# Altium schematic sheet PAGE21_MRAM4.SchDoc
size 381 x 381 mm; SheetNumber: 22; SheetTotal: 28
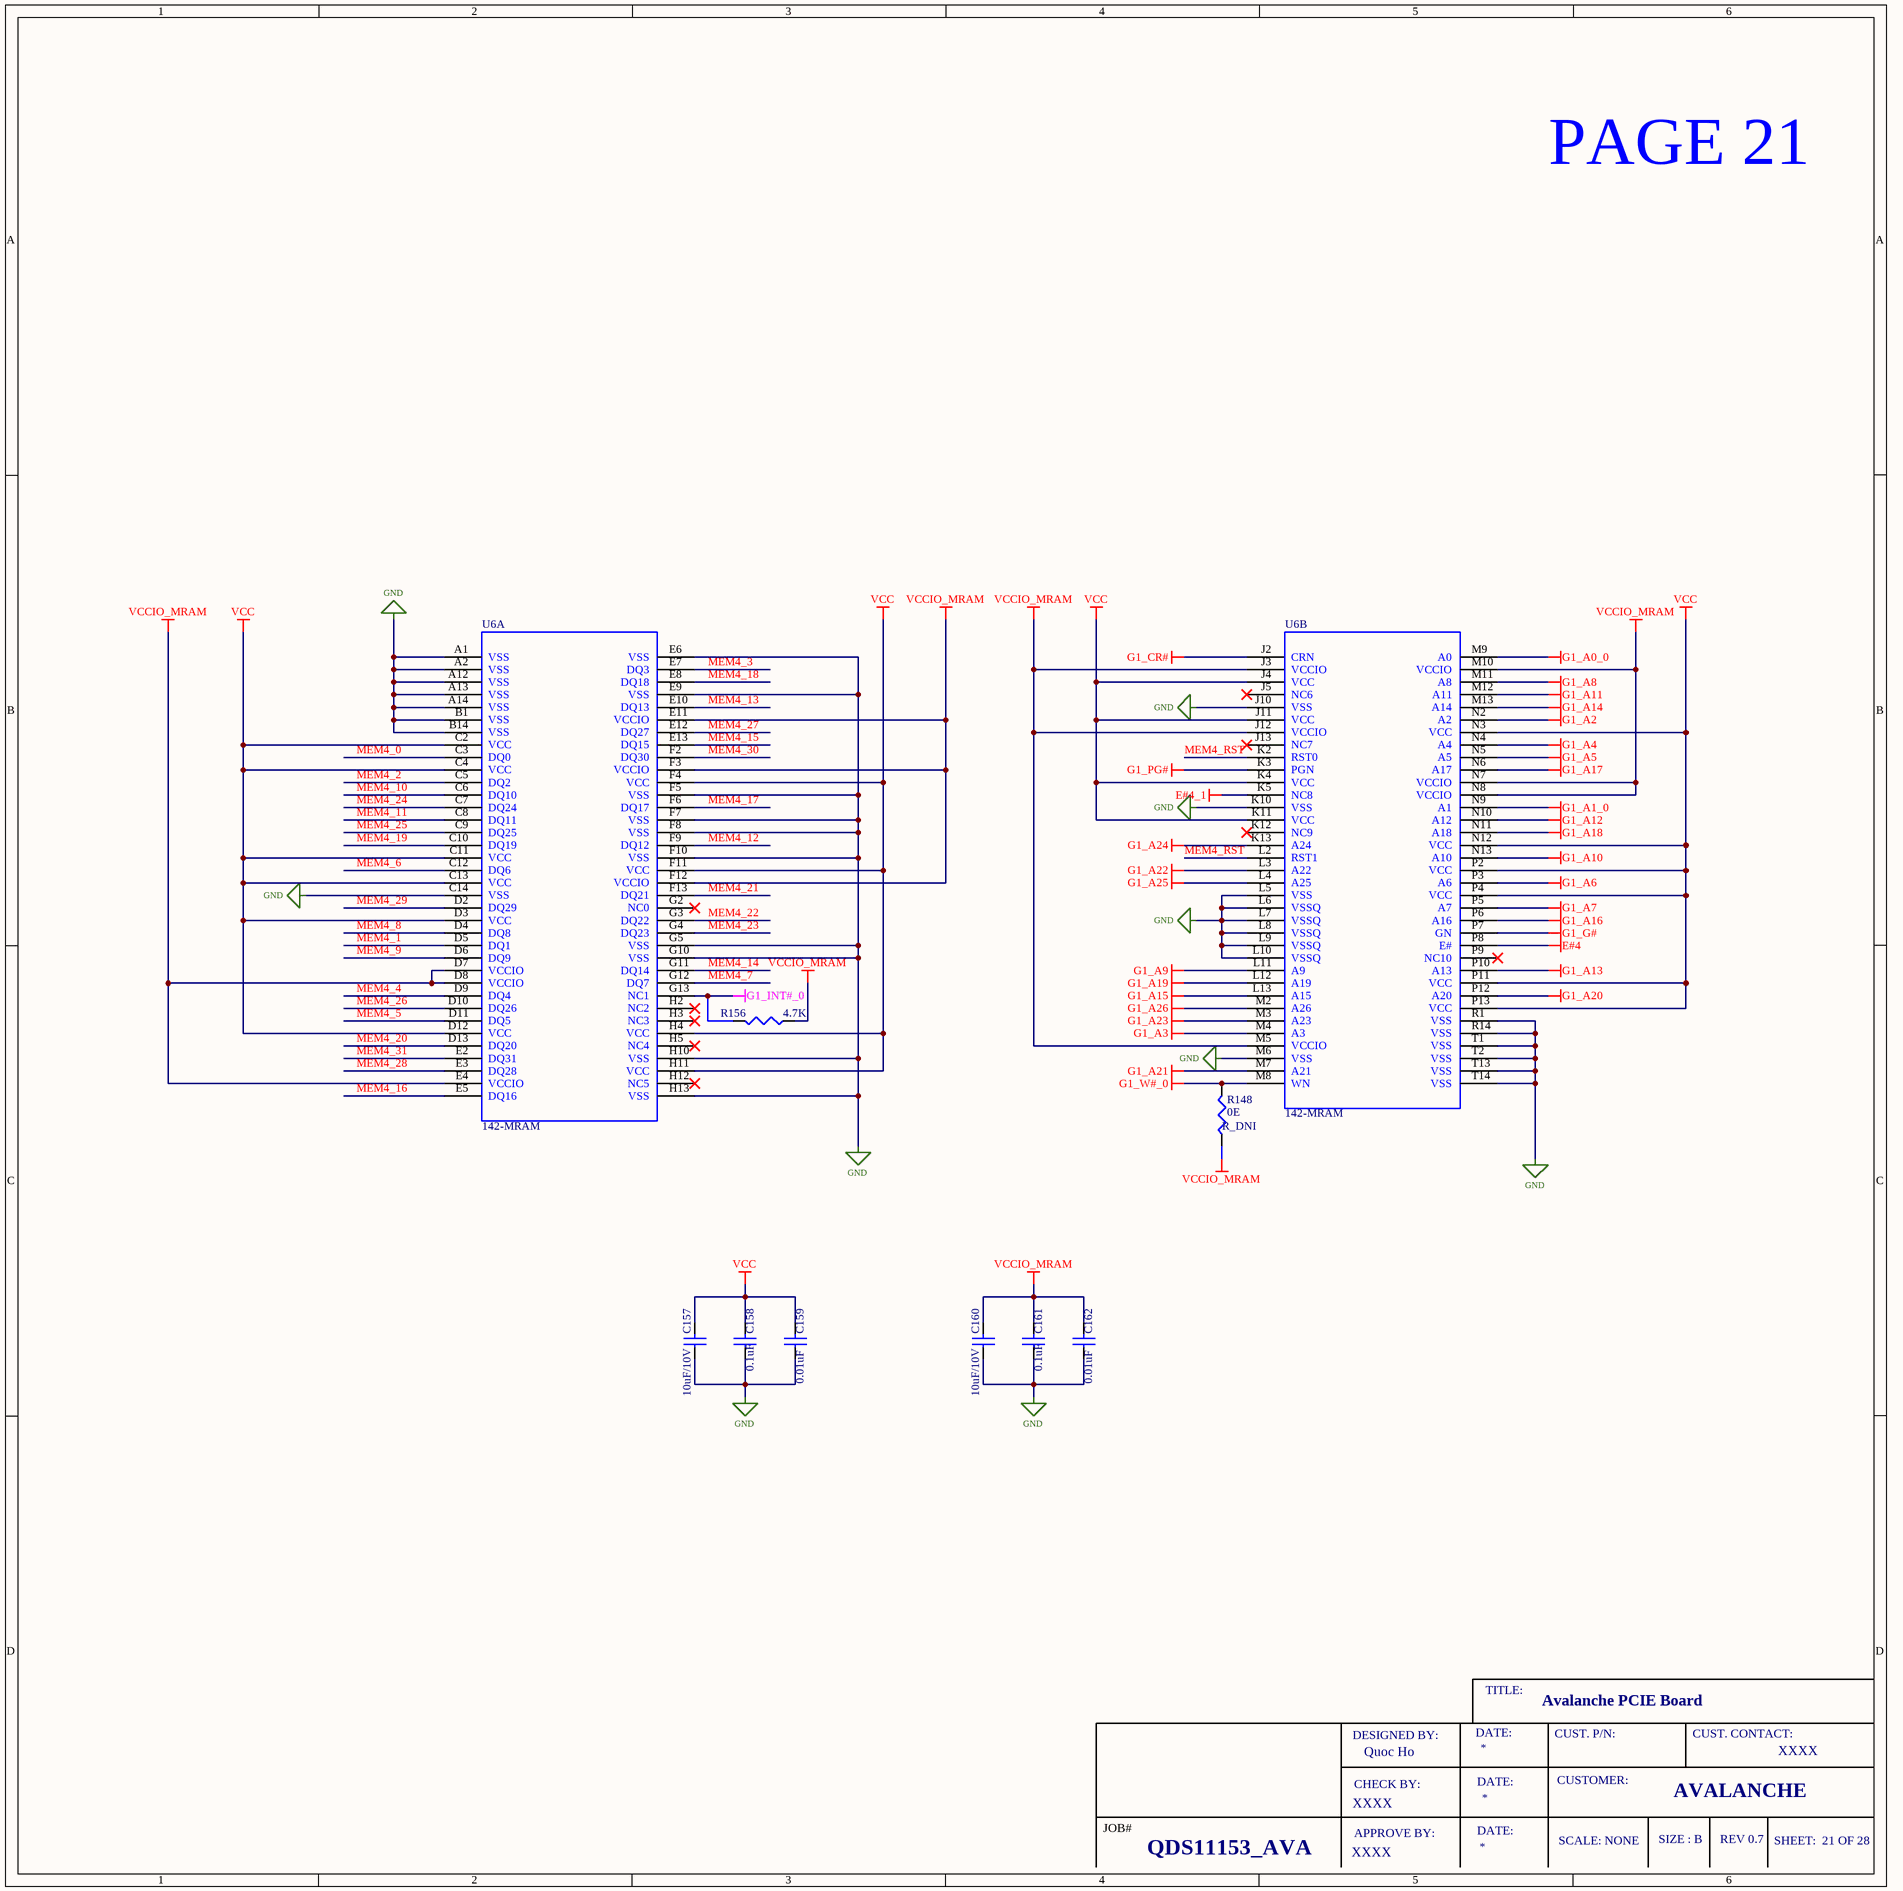
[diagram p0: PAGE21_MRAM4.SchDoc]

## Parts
C157  10uF/10V  [CN_0402]
C158  0.1uF  [CN_0402]
C159  0.01uF  [CN_0402]
C160  10uF/10V  [CN_0402]
C161  0.1uF  [CN_0402]
C162  0.01uF  [CN_0402]
R148  0E  [RN_0402]
R156  4.7K  [RN_0402]
U6  142-MRAM  [142-MRAM]  (parts A,B of 2)

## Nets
E#4: U6.P8(E#)
E#4_1: U6.K5(NC8)
G1_A0_0: U6.M9(A0)
G1_A1_0: U6.N9(A1)
G1_A2: U6.N2(A2)
G1_A3: U6.M4(A3)
G1_A4: U6.N4(A4)
G1_A5: U6.N5(A5)
G1_A6: U6.P3(A6)
G1_A7: U6.P5(A7)
G1_A8: U6.M11(A8)
G1_A9: U6.L11(A9)
G1_A10: U6.N13(A10)
G1_A11: U6.M12(A11)
G1_A12: U6.N10(A12)
G1_A13: U6.P10(A13)
G1_A14: U6.M13(A14)
G1_A15: U6.L13(A15)
G1_A16: U6.P6(A16)
G1_A17: U6.N6(A17)
G1_A18: U6.N11(A18)
G1_A19: U6.L12(A19)
G1_A20: U6.P12(A20)
G1_A21: U6.M7(A21)
G1_A22: U6.L3(A22)
G1_A23: U6.M3(A23)
G1_A24: U6.K13(A24)
G1_A25: U6.L4(A25)
G1_A26: U6.M2(A26)
G1_CR#: U6.J2(CRN)
G1_G#: U6.P7(GN)
G1_INT#_0: R156.2 U6.G13(NC1)
G1_PG#: U6.K3(PGN)
G1_W#_0: R148.2 U6.M8(WN)
GND: C157.1 C158.1 C159.1 C160.1 C161.1 C162.1 U6.A1(VSS) U6.A2(VSS) U6.A12(VSS) U6.A13(VSS) U6.A14(VSS) U6.B1(VSS) U6.B14(VSS) U6.C14(VSS) U6.E6(VSS) U6.E9(VSS) U6.F5(VSS) U6.F7(VSS) U6.F8(VSS) U6.F10(VSS) U6.G5(VSS) U6.G10(VSS) U6.H10(VSS) U6.H13(VSS) U6.J10(VSS) U6.K10(VSS) U6.L5(VSS) U6.L6(VSSQ) U6.L7(VSSQ) U6.L8(VSSQ) U6.L9(VSSQ) U6.L10(VSSQ) U6.M6(VSS) U6.R1(VSS) U6.R14(VSS) U6.T1(VSS) U6.T2(VSS) U6.T13(VSS) U6.T14(VSS)
VCC: C157.2 C158.2 C159.2 U6.C2(VCC) U6.C4(VCC) U6.C11(VCC) U6.C13(VCC) U6.D3(VCC) U6.D12(VCC) U6.F4(VCC) U6.F11(VCC) U6.H4(VCC) U6.H11(VCC) U6.J4(VCC) U6.J11(VCC) U6.K4(VCC) U6.K11(VCC) U6.N3(VCC) U6.N12(VCC) U6.P2(VCC) U6.P4(VCC) U6.P11(VCC) U6.P13(VCC)
VCCIO_MRAM: C160.2 C161.2 C162.2 R148.1 R156.1 U6.D7(VCCIO) U6.D8(VCCIO) U6.E4(VCCIO) U6.E11(VCCIO) U6.F3(VCCIO) U6.F12(VCCIO) U6.J3(VCCIO) U6.J12(VCCIO) U6.M5(VCCIO) U6.M10(VCCIO) U6.N7(VCCIO) U6.N8(VCCIO)
MEM4_0: U6.C3(DQ0)
MEM4_1: U6.D5(DQ1)
MEM4_2: U6.C5(DQ2)
MEM4_3: U6.E7(DQ3)
MEM4_4: U6.D9(DQ4)
MEM4_5: U6.D11(DQ5)
MEM4_6: U6.C12(DQ6)
MEM4_7: U6.G12(DQ7)
MEM4_8: U6.D4(DQ8)
MEM4_9: U6.D6(DQ9)
MEM4_10: U6.C6(DQ10)
MEM4_11: U6.C8(DQ11)
MEM4_12: U6.F9(DQ12)
MEM4_13: U6.E10(DQ13)
MEM4_14: U6.G11(DQ14)
MEM4_15: U6.E13(DQ15)
MEM4_16: U6.E5(DQ16)
MEM4_17: U6.F6(DQ17)
MEM4_18: U6.E8(DQ18)
MEM4_19: U6.C10(DQ19)
MEM4_20: U6.D13(DQ20)
MEM4_21: U6.F13(DQ21)
MEM4_22: U6.G3(DQ22)
MEM4_23: U6.G4(DQ23)
MEM4_24: U6.C7(DQ24)
MEM4_25: U6.C9(DQ25)
MEM4_26: U6.D10(DQ26)
MEM4_27: U6.E12(DQ27)
MEM4_28: U6.E3(DQ28)
MEM4_29: U6.D2(DQ29)
MEM4_30: U6.F2(DQ30)
MEM4_31: U6.E2(DQ31)
MEM4_RST: U6.K2(RST0) U6.L2(RST1)

Not connected (* = marked no-connect by the designer): U6 G2(NC0)* H2(NC2)* H3(NC3)* H5(NC4)* H12(NC5)* J5(NC6)* J13(NC7)* K12(NC9)* P9(NC10)*

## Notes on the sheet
- PAGE 21
- TITLE:
- Avalanche PCIE Board
- DESIGNED BY:
- CHECK BY:
- Quoc Ho
- DATE:
- CUST. P/N:
- CUSTOMER:
- CUST. CONTACT:
- XXXX
- JOB#
- APPROVE BY:
- SCALE: NONE
- SIZE : B
- AVALANCHE
- REV 0.7
- SHEET:  21 OF 28
- QDS11153_AVA

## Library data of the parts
C157 = CAP: CAP CER 10UF 10V X5R 0402; Manufacturer: Murata Electronics; Manufacturer Part Number: GRM155R61A106ME11D
C158 C161 = CAP: CAP CER 0.1UF 50V X7R 0402; Manufacturer: Murata Electronics; Manufacturer Part Number: GCM155R71H104KE02J
C159 = CAP: 0.01 µF, 25 V, 0402 [1005 Metric], ± 10%, X7R; Manufacturer: YAGEO; Manufacturer Part Number: CC0402JRX7R8BB103
C160 = CAP: CAP CER 10UF 10V X5R 0402; Manufacturer Part Number: GRM155R61A106ME11D; Manufacturer: Murata Electronics
C162 = CAP: 0.01 µF, 25 V, 0402 [1005 Metric], ± 10%, X7R; Manufacturer Part Number: CC0402JRX7R8BB103; Manufacturer: YAGEO
R148 = RES: RES 0 OHM JUMPER 1/16W 0402; Manufacturer: YAGEO; Manufacturer Part Number: RC0402FR-070RL
R156 = RES: RES 4.7K OHM 1% 1/16W 0402; Manufacturer Part Number: RC0402FR-134K7L; Manufacturer: YAGEO
U6 = 142-MRAM: IC 142-MRAM MEMORY; Manufacturer: Avalanche Technology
